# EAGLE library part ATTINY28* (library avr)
MICROCONTROLLER 1.8 V 2 Kbytes FLASH
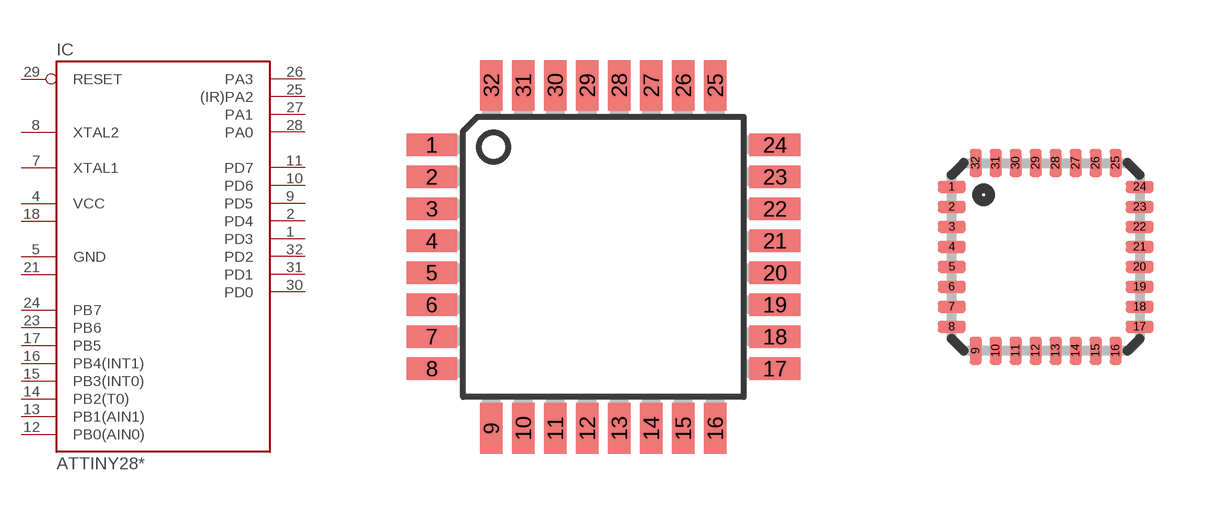
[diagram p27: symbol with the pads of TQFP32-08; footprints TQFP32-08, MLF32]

Designator prefix IC

## ATTINY28L-4A, ATTINY28V-1A  [TQFP32-08]
1  PD3
2  PD4
3  NC1  nc
4  VCC  pwr
5  GND  pwr
6  NC2  nc
7  XTAL1
8  XTAL2
9  PD5
10  PD6
11  PD7
12  PB0(AIN0)  in
13  PB1(AIN1)  in
14  PB2(T0)  in
15  PB3(INT0)  in
16  PB4(INT1)  in
17  PB5  in
18  VCC1  pwr
19  NC3  nc
20  NC4  nc
21  GND1  pwr
22  NC5  nc
23  PB6  in
24  PB7  in
25  (IR)PA2  out
26  PA3
27  PA1
28  PA0
29  RESET  in
30  PD0
31  PD1
32  PD2

## ATTINY28L-4M, ATTINY28V-1M  [MLF32]
Pads as for TQFP32-08

## Footprint TQFP32-08 (pad centres in mm)
Thin Plasic Quad Flat Package Grid 0.8 mm
smd 1.27 x 0.559: 1 -4.293,2.8; 2 -4.293,2; 3 -4.293,1.2; 4 -4.293,0.4; 5 -4.293,-0.4; 6 -4.293,-1.2; 7 -4.293,-2; 8 -4.293,-2.8; 17 4.293,-2.8; 18 4.293,-2; 19 4.293,-1.2; 20 4.293,-0.4; 21 4.293,0.4; 22 4.293,1.2; 23 4.293,2; 24 4.293,2.8
smd 0.559 x 1.27: 9 -2.8,-4.293; 10 -2,-4.293; 11 -1.2,-4.293; 12 -0.4,-4.293; 13 0.4,-4.293; 14 1.2,-4.293; 15 2,-4.293; 16 2.8,-4.293; 25 2.8,4.293; 26 2,4.293; 27 1.2,4.293; 28 0.4,4.293; 29 -0.4,4.293; 30 -1.2,4.293; 31 -2,4.293; 32 -2.8,4.293

## Footprint MLF32 (pad centres in mm)
32M1-A Micro Lead Frame package (MLF)
smd 0.7 x 0.3: 1 -2.35,1.75; 2 -2.35,1.25; 3 -2.35,0.75; 4 -2.35,0.25; 5 -2.35,-0.25; 6 -2.35,-0.75; 7 -2.35,-1.25; 8 -2.35,-1.75; 17 2.35,-1.75; 18 2.35,-1.25; 19 2.35,-0.75; 20 2.35,-0.25; 21 2.35,0.25; 22 2.35,0.75; 23 2.35,1.25; 24 2.35,1.75
smd 0.3 x 0.7: 9 -1.75,-2.35; 10 -1.25,-2.35; 11 -0.75,-2.35; 12 -0.25,-2.35; 13 0.25,-2.35; 14 0.75,-2.35; 15 1.25,-2.35; 16 1.75,-2.35; 25 1.75,2.35; 26 1.25,2.35; 27 0.75,2.35; 28 0.25,2.35; 29 -0.25,2.35; 30 -0.75,2.35; 31 -1.25,2.35; 32 -1.75,2.35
